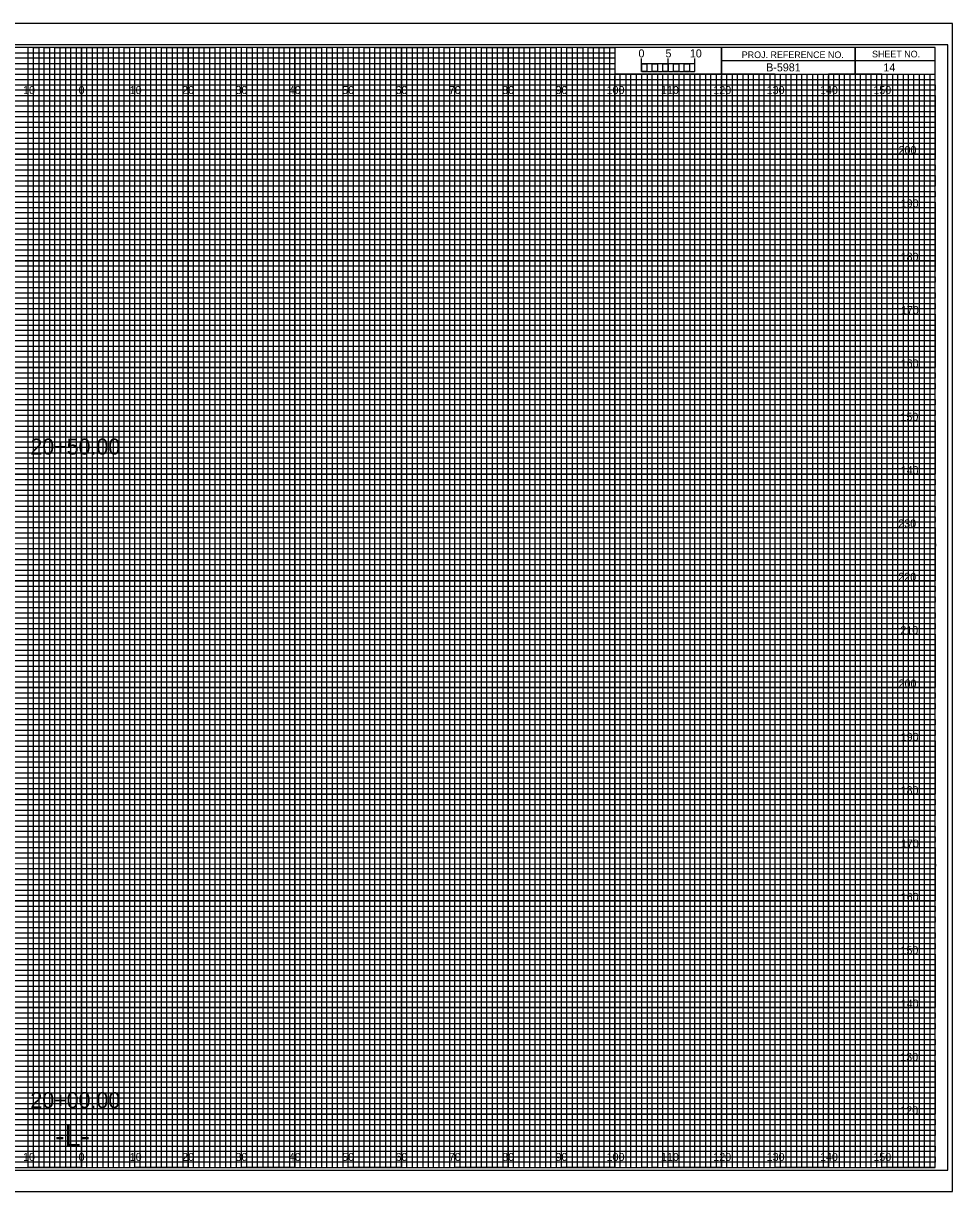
# Model space of a CAD drawing. Extents: x -13 to 323, y -5 to 4174.
# Drawn here: x 149.1 to 323.3, y 1755.5 to 1974.5 of the extents above; entities that cross this region are included whole.
import ezdxf

# ---------------------------------------------------------------- set-up
doc = ezdxf.new("R2010")
doc.units = 0
for name, color, linetype in [('Exist Cross Section Cell', 7, 'Continuous'), ('Exist XS Center Line Elevation Label', 7, 'Continuous'), ('Exist XS Ground Line', 7, 'Continuous'), ('Prop CMT Concrete Structures', 7, 'Continuous'), ('Prop CMT Guardrail Graphics', 7, 'Continuous'), ('Prop CMT Pvmt Course 1', 7, 'Continuous'), ('Prop CMT Pvmt Course 2', 7, 'Continuous'), ('Prop CMT Pvmt Course 3', 7, 'Continuous'), ('Prop CMT Pvmt Surface', 7, 'Continuous'), ('Prop CMT Shld Paved Course 1', 7, 'Continuous'), ('Prop CMT Shld Paved Course 2', 7, 'Continuous'), ('Prop CMT Shld Paved Course 3', 7, 'Continuous'), ('Prop CMT Subgrade Earthwork', 7, 'Continuous'), ('Prop XS Ditch Standard Text', 7, 'Continuous'), ('Prop XS SE Text', 7, 'Continuous'), ('Prop XS Side Slope Text', 7, 'Continuous'), ('Scratch_Level_0', 7, 'Continuous')]:
    doc.layers.add(name, color=color, linetype=linetype)

msp = doc.modelspace()

# ---------------------------------------------------------------- linework, layer by layer
at = {"layer": 'Exist XS Center Line Elevation Label'}
for points in [[(145, 1760), (155, 1760), (155, 1970), (165, 1970), (165, 1760), (175, 1760), (175, 1970), (185, 1970), (185, 1760), (195, 1760), (195, 1970), (205, 1970), (205, 1760), (215, 1760), (215, 1970), (225, 1970), (225, 1760), (235, 1760), (235, 1970), (245, 1970), (245, 1760), (255, 1760), (255, 1970), (259.93, 1970), (260, 1970), (260, 1965), (264.99, 1965), (264.99, 1760), (275, 1760), (275, 1965), (285, 1965), (285, 1760), (295, 1760), (295, 1965), (305, 1965), (305, 1760), (315, 1760), (315, 1965)], [(0, 1965), (275, 1965)], [(0, 1945), (320, 1945), (320, 1955), (0, 1955)], [(0, 1925), (320, 1925), (320, 1935), (0, 1935)], [(0, 1905), (320, 1905), (320, 1915), (0, 1915)], [(0, 1885), (320, 1885), (320, 1895), (0, 1895)], [(0, 1865), (320, 1865), (320, 1875), (0, 1875)], [(0, 1845), (320, 1845), (320, 1855), (0, 1855)], [(0, 1825), (320, 1825), (320, 1835), (0, 1835)], [(0, 1805), (320, 1805), (320, 1815), (0, 1815)], [(0, 1785), (320, 1785), (320, 1795), (0, 1795)], [(0, 1765), (320, 1765), (320, 1775), (0, 1775)]]:
    msp.add_lwpolyline(points, dxfattribs=at)
at = {"layer": 'Exist XS Ground Line'}
for p, q in [((150, 1970), (140, 1970)), ((150, 1760), (150, 1970)), ((170, 1970), (160, 1970)), ((160, 1970), (160, 1760)), ((170, 1760), (170, 1970)), ((190, 1970), (180, 1970)), ((180, 1970), (180, 1760)), ((190, 1760), (190, 1970)), ((210, 1970), (200, 1970)), ((200, 1970), (200, 1760)), ((210, 1760), (210, 1970)), ((230, 1970), (220, 1970)), ((220, 1970), (220, 1760)), ((230, 1760), (230, 1970)), ((250, 1970), (240, 1970)), ((240, 1970), (240, 1760)), ((250, 1760), (250, 1970)), ((260, 1970), (260, 1760)), ((270, 1760), (270, 1965)), ((290, 1965), (280, 1965)), ((280, 1965), (280, 1760)), ((290, 1760), (290, 1965)), ((310, 1965), (300, 1965)), ((300, 1965), (300, 1760)), ((310, 1760), (310, 1965)), ((160, 1760), (150, 1760)), ((180, 1760), (170, 1760)), ((200, 1760), (190, 1760)), ((220, 1760), (210, 1760)), ((240, 1760), (230, 1760)), ((260, 1760), (250, 1760)), ((280, 1760), (270, 1760)), ((300, 1760), (290, 1760)), ((320, 1760), (310, 1760)), ((320, 1760), (320, 1760))]:
    msp.add_line(p, q, dxfattribs=at)
for points in [[(0, 1960), (320, 1960), (320, 1950), (0, 1950)], [(0, 1940), (320, 1940), (320, 1930), (0, 1930)], [(0, 1920), (320, 1920), (320, 1910), (0, 1910)], [(0, 1900), (320, 1900), (320, 1890), (0, 1890)], [(0, 1880), (320, 1880), (320, 1870), (0, 1870)], [(0, 1860), (320, 1860), (320, 1850), (0, 1850)], [(0, 1840), (320, 1840), (320, 1830), (0, 1830)], [(0, 1820), (320, 1820), (320, 1810), (0, 1810)], [(0, 1800), (320, 1800), (320, 1790), (0, 1790)], [(0, 1780), (320, 1780), (320, 1770), (0, 1770)]]:
    msp.add_lwpolyline(points, dxfattribs=at)
at = {"layer": 'Prop CMT Pvmt Course 1'}
for p, q in [((323.3, 1974.5), (-13.4, 1974.5)), ((-13.4, 1755.5), (323.3, 1755.5))]:
    msp.add_line(p, q, dxfattribs=at)
at = {"layer": 'Prop CMT Pvmt Course 2'}
msp.add_lwpolyline([(-13.4, 1755.5), (323.3, 1755.5), (323.3, 1974.5), (-13.4, 1974.5)], close=True, dxfattribs=at)
at = {"layer": 'Prop CMT Pvmt Course 3'}
msp.add_lwpolyline([(-10.8, 1759.5), (322.4, 1759.5), (322.4, 1970.5), (-10.8, 1970.5)], close=True, dxfattribs=at)
at = {"layer": 'Prop CMT Shld Paved Course 1'}
for p, q in [((305, 1970), (305, 1965)), ((305, 1965), (305, 1970)), ((280, 1967.5), (280, 1965)), ((320, 1967.49), (280, 1967.49)), ((280, 1965), (320, 1965))]:
    msp.add_line(p, q, dxfattribs=at)
for points in [[(320, 1970), (0, 1970), (0, 1760), (320, 1760)], [(280, 1970), (260, 1970), (260, 1965.03), (280, 1965.03)], [(320, 1970), (280, 1970), (280, 1965), (320, 1965)]]:
    msp.add_lwpolyline(points, close=True, dxfattribs=at)
at = {"layer": 'Prop CMT Shld Paved Course 2'}
for p, q in [((267, 1965), (266.01, 1965)), ((266.01, 1965), (266.01, 1760)), ((267, 1760), (267, 1965)), ((269, 1965), (268, 1965)), ((268, 1965), (268, 1760)), ((269, 1760), (269, 1965)), ((266.01, 1760), (265, 1760)), ((268, 1760), (267, 1760))]:
    msp.add_line(p, q, dxfattribs=at)
for points in [[(150, 1760), (151, 1760), (151, 1970), (152, 1970), (152, 1760)], [(152, 1760), (153, 1760), (153, 1970), (154, 1970), (154, 1760)], [(155, 1760), (156, 1760), (156, 1970), (157, 1970), (157, 1760)], [(157, 1760), (158, 1760), (158, 1970), (159, 1970), (159, 1760)], [(160, 1760), (161, 1760), (161, 1970), (162, 1970), (162, 1760)], [(162, 1760), (163, 1760), (163, 1970), (164, 1970), (164, 1760)], [(165, 1760), (166, 1760), (166, 1970), (167, 1970), (167, 1760)], [(167, 1760), (168, 1760), (168, 1970), (169, 1970), (169, 1760)], [(170, 1760), (171, 1760), (171, 1970), (172, 1970), (172, 1760)], [(172, 1760), (173, 1760), (173, 1970), (174, 1970), (174, 1760)], [(175, 1760), (176, 1760), (176, 1970), (177, 1970), (177, 1760)], [(177, 1760), (178, 1760), (178, 1970), (179, 1970), (179, 1760)], [(180, 1760), (181, 1760), (181, 1970), (182, 1970), (182, 1760)], [(182, 1760), (183, 1760), (183, 1970), (184, 1970), (184, 1760)], [(185, 1760), (186, 1760), (186, 1970), (187, 1970), (187, 1760)], [(187, 1760), (188, 1760), (188, 1970), (189, 1970), (189, 1760)], [(190, 1760), (191, 1760), (191, 1970), (192, 1970), (192, 1760)], [(192, 1760), (193, 1760), (193, 1970), (194, 1970), (194, 1760)], [(195, 1760), (196, 1760), (196, 1970), (197, 1970), (197, 1760)], [(197, 1760), (198, 1760), (198, 1970), (199, 1970), (199, 1760)], [(200, 1760), (201, 1760), (201, 1970), (202, 1970), (202, 1760)], [(202, 1760), (203, 1760), (203, 1970), (204, 1970), (204, 1760)], [(205, 1760), (206, 1760), (206, 1970), (207, 1970), (207, 1760)], [(207, 1760), (208, 1760), (208, 1970), (209, 1970), (209, 1760)], [(210, 1760), (211, 1760), (211, 1970), (212, 1970), (212, 1760)], [(212, 1760), (213, 1760), (213, 1970), (214, 1970), (214, 1760)], [(215, 1760), (216, 1760), (216, 1970), (217, 1970), (217, 1760)], [(217, 1760), (218, 1760), (218, 1970), (219, 1970), (219, 1760)], [(220, 1760), (221, 1760), (221, 1970), (222, 1970), (222, 1760)], [(222, 1760), (223, 1760), (223, 1970), (224, 1970), (224, 1760)], [(225, 1760), (226, 1760), (226, 1970), (227, 1970), (227, 1760)], [(227, 1760), (228, 1760), (228, 1970), (229, 1970), (229, 1760)], [(230, 1760), (231, 1760), (231, 1970), (232, 1970), (232, 1760)], [(232, 1760), (233, 1760), (233, 1970), (234, 1970), (234, 1760)], [(235, 1760), (236, 1760), (236, 1970), (237, 1970), (237, 1760)], [(237, 1760), (238, 1760), (238, 1970), (239, 1970), (239, 1760)], [(240, 1760), (241, 1760), (241, 1970), (242, 1970), (242, 1760)], [(242, 1760), (243, 1760), (243, 1970), (244, 1970), (244, 1760)], [(245, 1760), (246, 1760), (246, 1970), (247, 1970), (247, 1760)], [(247, 1760), (248, 1760), (248, 1970), (249, 1970), (249, 1760)], [(250, 1760), (251, 1760), (251, 1970), (252, 1970), (252, 1760)], [(252, 1760), (253, 1760), (253, 1970), (254, 1970), (254, 1760)], [(255, 1760), (256, 1760), (256, 1970), (257, 1970), (257, 1760)], [(257, 1760), (258, 1760), (258, 1970), (259, 1970), (259, 1760)], [(260, 1760), (261, 1760), (261, 1965), (262.02, 1965), (262.02, 1760)], [(262, 1760), (263, 1760), (263, 1965), (263.99, 1965), (263.99, 1760)], [(270, 1760), (270.98, 1760), (270.98, 1965), (272, 1965), (272, 1760)], [(272, 1760), (273, 1760), (273, 1965), (274.05, 1965), (274.05, 1760)], [(275, 1760), (276, 1760), (276, 1965), (277, 1965), (277, 1760)], [(277, 1760), (278, 1760), (278, 1965), (279, 1965), (279, 1760)], [(280, 1760), (281, 1760), (281, 1965), (282, 1965), (282, 1760)], [(282, 1760), (283, 1760), (283, 1965), (284, 1965), (284, 1760)], [(285, 1760), (286, 1760), (286, 1965), (287, 1965), (287, 1760)], [(287, 1760), (288, 1760), (288, 1965), (289, 1965), (289, 1760)], [(290, 1760), (291, 1760), (291, 1965), (292, 1965), (292, 1760)], [(292, 1760), (293, 1760), (293, 1965), (294, 1965), (294, 1760)], [(295, 1760), (296, 1760), (296, 1965), (297, 1965), (297, 1760)], [(297, 1760), (298, 1760), (298, 1965), (299, 1965), (299, 1760)], [(300, 1760), (301, 1760), (301, 1965), (302, 1965), (302, 1760)], [(302, 1760), (303, 1760), (303, 1965), (304, 1965), (304, 1760)], [(305, 1760), (306, 1760), (306, 1965), (307, 1965), (307, 1760)], [(307, 1760), (308, 1760), (308, 1965), (309, 1965), (309, 1760)], [(310, 1760), (311, 1760), (311, 1965), (312, 1965), (312, 1760)], [(312, 1760), (313, 1760), (313, 1965), (314, 1965), (314, 1760)], [(315, 1760), (316, 1760), (316, 1965), (317, 1965), (317, 1760)], [(317, 1760), (318, 1760), (318, 1965), (319, 1965), (319, 1760)]]:
    msp.add_lwpolyline(points, dxfattribs=at)
at = {"layer": 'Prop CMT Shld Paved Course 3'}
for p, q in [((265, 1965.49), (265, 1967.9)), ((265, 1966.9), (265, 1967.9)), ((270, 1965.49), (270, 1967.9)), ((275, 1965.49), (275, 1967.9)), ((275, 1966.9), (275, 1967.9))]:
    msp.add_line(p, q, dxfattribs=at)
for points in [[(275, 1966.9), (265, 1966.9), (265, 1965.49), (275, 1965.49)], [(265, 1966.9), (266, 1966.9), (266, 1965.49), (265, 1965.49)], [(267, 1966.9), (268, 1966.9), (268, 1965.49), (267, 1965.49)], [(269, 1966.9), (270, 1966.9), (270, 1965.49), (269, 1965.49)], [(271, 1966.9), (272, 1966.9), (272, 1965.49), (271, 1965.49)], [(273, 1966.9), (274, 1966.9), (274, 1965.49), (273, 1965.49)]]:
    msp.add_lwpolyline(points, close=True, dxfattribs=at)
at = {"layer": 'Prop CMT Subgrade Earthwork'}
for p, q in [((150, 1760), (150, 1970)), ((160, 1760), (160, 1970)), ((170, 1760), (170, 1970)), ((180, 1760), (180, 1970)), ((190, 1760), (190, 1970)), ((200, 1760), (200, 1970)), ((210, 1760), (210, 1970)), ((220, 1760), (220, 1970)), ((230, 1760), (230, 1970)), ((240, 1760), (240, 1970)), ((250, 1760), (250, 1970)), ((260, 1760), (260, 1964.69)), ((270, 1760), (270, 1964.69)), ((280, 1760), (280, 1964.69)), ((290, 1760), (290, 1964.69)), ((300, 1760), (300, 1964.69)), ((310, 1760), (310, 1964.69)), ((0, 1960), (320, 1960)), ((0, 1950), (320, 1950)), ((0, 1940), (320, 1940)), ((0, 1930), (320, 1930)), ((0, 1920), (320, 1920)), ((0, 1910), (320, 1910)), ((0, 1900), (320, 1900)), ((0, 1890), (320, 1890)), ((0, 1880), (320, 1880)), ((0, 1870), (320, 1870)), ((0, 1860), (320, 1860)), ((0, 1850), (320, 1850)), ((0, 1840), (320, 1840)), ((0, 1830), (320, 1830)), ((0, 1820), (320, 1820)), ((0, 1810), (320, 1810)), ((0, 1800), (320, 1800)), ((0, 1790), (320, 1790)), ((0, 1780), (320, 1780)), ((0, 1770), (320, 1770))]:
    msp.add_line(p, q, dxfattribs=at)
at = {"layer": 'Scratch_Level_0'}
for p, q in [((0, 1969), (260, 1969)), ((260, 1969), (260, 1967.98)), ((260, 1967.98), (0, 1967.98)), ((0, 1967), (260, 1967)), ((260, 1967), (260, 1965.89)), ((260, 1965.89), (0, 1965.89)), ((0, 1964), (320, 1964))]:
    msp.add_line(p, q, dxfattribs=at)
for points in [[(0, 1963), (270, 1963), (320, 1963), (320, 1962), (0, 1962)], [(0, 1961), (320, 1961), (320, 1959), (0, 1959)], [(0, 1958), (320, 1958), (320, 1957), (0, 1956.98)], [(0, 1956), (320, 1956), (320, 1954), (0, 1954)], [(0, 1953), (320, 1953), (320, 1952), (0, 1952)], [(0, 1951), (320, 1951), (320, 1949), (0, 1949)], [(0, 1948), (320, 1948), (320, 1947), (0, 1947)], [(0, 1946), (320, 1946), (320, 1944), (0, 1944)], [(0, 1943), (320, 1943), (320, 1942), (0, 1942)], [(0, 1941), (320, 1941), (320, 1939), (0, 1939)], [(0, 1938), (320, 1938), (320, 1937), (0, 1937)], [(0, 1936), (320, 1936), (320, 1933.95), (320, 1933), (320, 1932), (0, 1932)], [(0, 1934), (320, 1934), (320, 1933), (0, 1933)], [(0, 1931), (320, 1931), (320, 1929), (0, 1929.03)], [(0, 1929.03), (320, 1929), (320, 1928), (0, 1928)], [(0, 1927), (320, 1927), (320, 1926), (0, 1926)], [(0, 1924), (320, 1924), (320, 1923), (0, 1923)], [(0, 1922), (320, 1922), (320, 1921), (0, 1921)], [(-0.07, 1918.89), (320, 1918.89), (320, 1917.88), (-0.07, 1917.88)], [(0, 1917), (320, 1917), (320, 1916), (0, 1916)], [(0, 1914), (320, 1914), (320, 1913), (0, 1913)], [(0, 1912), (320, 1912), (320, 1911), (0, 1911)], [(0, 1909), (320, 1909), (320, 1908), (0, 1908)], [(0, 1907), (320, 1907), (320, 1906), (0, 1906)], [(0, 1904), (320, 1904), (320, 1903), (0, 1903)], [(0, 1902), (320, 1902), (320, 1901), (0, 1901)], [(0, 1899), (320, 1899), (319.99, 1897.98), (0, 1898)], [(0, 1897), (320, 1897), (320, 1896), (0, 1896)], [(0, 1894), (320, 1894), (320, 1893), (0, 1893)], [(0, 1892), (320, 1892), (320, 1891), (0, 1891)], [(0, 1889), (320, 1889), (320, 1888), (0, 1888)], [(0, 1887), (320, 1887), (320, 1886), (0, 1886)], [(0, 1884), (320, 1884), (320, 1883), (0, 1883)], [(0, 1882), (320, 1882), (320, 1881), (0, 1881)], [(0, 1879), (320, 1879), (320, 1878), (0, 1878)], [(0, 1876.99), (320.07, 1876.91), (320, 1876), (0, 1876)], [(0, 1874), (320, 1874), (320, 1873), (0, 1873)], [(0, 1872), (320, 1872), (320, 1871), (0, 1871)], [(0, 1869), (320, 1869), (320, 1868), (0, 1868)], [(0, 1867), (320, 1867), (320, 1866), (0, 1866)], [(0, 1864), (320, 1864), (320, 1863), (0, 1863)], [(0, 1862), (320, 1862), (320, 1861), (0, 1861)], [(0, 1859), (320, 1859), (320, 1858), (0, 1858)], [(0, 1857), (320, 1857), (320, 1856), (0, 1856)], [(0, 1854), (320, 1854), (320, 1853), (0, 1853)], [(0, 1852), (320, 1852), (320, 1851), (0, 1851)], [(0, 1849), (320, 1849), (320, 1848), (0, 1848)], [(0, 1847), (320, 1847), (320, 1846), (0, 1846)], [(0, 1844), (320, 1844), (320, 1843), (0, 1843)], [(0, 1842), (320, 1842), (320, 1841), (0, 1841)], [(0, 1839), (320, 1839), (319.99, 1837.98), (0, 1838)], [(0, 1837), (320, 1837), (320, 1836), (0, 1836)], [(0, 1834), (320, 1834), (320, 1833), (0, 1833)], [(0, 1832), (320, 1832), (320, 1831), (0, 1831)], [(0, 1829), (320, 1829), (320, 1828), (0, 1828)], [(0, 1827), (320, 1827), (320, 1826), (0, 1826)], [(0, 1824), (320, 1824), (320, 1823), (0, 1823)], [(0, 1822), (320, 1822), (320, 1821), (0, 1821)], [(0, 1819), (320, 1819), (320, 1818), (0, 1818)], [(0, 1816.99), (320.07, 1816.91), (320, 1816), (0, 1816)], [(0, 1814), (320, 1814), (320, 1813), (0, 1813)], [(0, 1812), (320, 1812), (320, 1811), (0, 1811)], [(0, 1809), (320, 1809), (320, 1808), (0, 1808)], [(0, 1807), (320, 1807), (320, 1806), (0, 1806)], [(0, 1804), (320, 1804), (320, 1803), (0, 1803)], [(0, 1802), (320, 1802), (320, 1801), (0, 1801)], [(0, 1799), (320, 1799), (320, 1798), (0, 1798)], [(0, 1797), (320, 1797), (320, 1796), (0, 1796)], [(0, 1794), (320, 1794), (320, 1793), (0, 1793)], [(0, 1792), (320, 1792), (320, 1791), (0, 1791)], [(0, 1789), (320, 1789), (320, 1788), (0, 1788)], [(0, 1787), (320, 1787), (320, 1786), (0, 1786)], [(0, 1784), (320, 1784), (320, 1783), (0, 1783)], [(0, 1782), (320, 1782), (320, 1781), (0, 1781)], [(0, 1779), (320, 1779), (320, 1778), (0, 1778)], [(0, 1777), (320, 1777), (320, 1776), (0, 1776)], [(0, 1774), (320, 1774), (320, 1773), (0, 1773)], [(0, 1772), (320, 1772), (320, 1771), (0, 1771)], [(0, 1769), (320, 1769), (320, 1768), (0, 1768)], [(0, 1767), (320, 1767), (320, 1766), (0, 1766)], [(0, 1764), (320, 1764), (320, 1763), (0, 1763)], [(0, 1762), (320, 1762), (320, 1761), (0, 1761)]]:
    msp.add_lwpolyline(points, dxfattribs=at)

# ---------------------------------------------------------------- texts
at = {"layer": 'Exist Cross Section Cell'}
for s, p in [('10', (149.04, 1961.25)), ('0', (159.45, 1961.25)), ('0', (159.45, 1961.25)), ('10', (169.04, 1961.25)), ('20', (178.86, 1961.25)), ('30', (188.86, 1961.25)), ('40', (198.86, 1961.25)), ('50', (208.86, 1961.25)), ('60', (218.86, 1961.25)), ('70', (228.86, 1961.25)), ('80', (238.86, 1961.25)), ('90', (248.86, 1961.25)), ('100', (258.44, 1961.25)), ('110', (268.62, 1961.25)), ('120', (278.44, 1961.25)), ('130', (288.44, 1961.25)), ('140', (298.44, 1961.25)), ('150', (308.44, 1961.25)), ('10', (149.04, 1761.25)), ('0', (159.45, 1761.25)), ('0', (159.45, 1761.25)), ('10', (169.04, 1761.25)), ('20', (178.86, 1761.25)), ('30', (188.86, 1761.25)), ('40', (198.86, 1761.25)), ('50', (208.86, 1761.25)), ('60', (218.86, 1761.25)), ('70', (228.86, 1761.25)), ('80', (238.86, 1761.25)), ('90', (248.86, 1761.25)), ('100', (258.44, 1761.25)), ('110', (268.62, 1761.25)), ('120', (278.44, 1761.25)), ('130', (288.44, 1761.25)), ('140', (298.44, 1761.25)), ('150', (308.44, 1761.25))]:
    msp.add_text(s, height=1.5, dxfattribs=at).set_placement(p)
at = {"layer": 'Prop CMT Concrete Structures'}
for s, p in [('20+50.00', (150.41, 1893.66)), ('20+00.00', (150.41, 1771.16))]:
    msp.add_text(s, height=3, dxfattribs=at).set_placement(p)
at = {"layer": 'Prop CMT Guardrail Graphics'}
for s, p in [('200', (313.17, 1950)), ('190', (313.57, 1940)), ('180', (313.55, 1930)), ('170', (313.61, 1920)), ('160', (313.57, 1910)), ('150', (313.52, 1900)), ('140', (313.57, 1890)), ('230', (313.11, 1880)), ('220', (313.12, 1870)), ('210', (313.5, 1860)), ('200', (313.17, 1850)), ('190', (313.57, 1840)), ('180', (313.55, 1830)), ('170', (313.61, 1820)), ('160', (313.57, 1810)), ('150', (313.52, 1800)), ('140', (313.57, 1790)), ('130', (313.49, 1780)), ('120', (313.5, 1770))]:
    msp.add_text(s, height=1.5, dxfattribs=at).set_placement(p)
at = {"layer": 'Prop CMT Pvmt Surface'}
for s, p in [('5', (269.47, 1968.12)), ('10', (274.04, 1968.12))]:
    msp.add_text(s, height=1.5, dxfattribs=at).set_placement(p)
at = {"layer": 'Prop CMT Shld Paved Course 1'}
for s, p in [('PROJ. REFERENCE NO.', (283.77, 1967.99)), ('SHEET NO.', (308.19, 1968.12))]:
    msp.add_text(s, height=1.25, dxfattribs=at).set_placement(p)
at = {"layer": 'Prop CMT Shld Paved Course 3'}
msp.add_text('0', height=1.5, dxfattribs=at).set_placement((264.41, 1968.12))
at = {"layer": 'Prop XS Ditch Standard Text'}
msp.add_text('-L-', height=4, dxfattribs=at).set_placement((155.06, 1764))
at = {"layer": 'Prop XS SE Text'}
msp.add_text(' B-5981', height=1.5, dxfattribs=at).set_placement((287.79, 1965.5))
at = {"layer": 'Prop XS Side Slope Text'}
msp.add_text('14', height=1.5, dxfattribs=at).set_placement((310.32, 1965.5))

doc.saveas('drawing.dxf')
